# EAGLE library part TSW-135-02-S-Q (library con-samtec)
THROUGH-HOLE .025" SQ POST HEADER Source: Samtec TSW.pdf
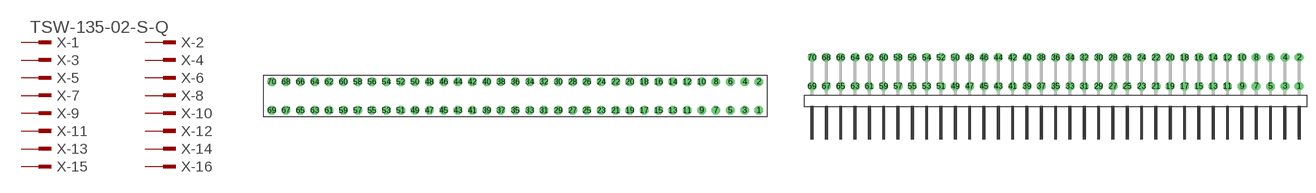
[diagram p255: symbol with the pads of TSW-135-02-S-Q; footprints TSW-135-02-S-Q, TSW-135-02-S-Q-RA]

Designator prefix X; gates -1=MPINV -2=MPIN -3=MPIN -4=MPIN -5=MPIN -6=MPIN -7=MPIN -8=MPIN -9=MPIN -10=MPIN -11=MPIN -12=MPIN -13=MPIN -14=MPIN -15=MPIN -16=MPIN -17=MPIN -18=MPIN -19=MPIN -20=MPIN -21=MPIN -22=MPIN -23=MPIN -24=MPIN -25=MPIN -26=MPIN -27=MPIN -28=MPIN -29=MPIN -30=MPIN -31=MPIN -32=MPIN -33=MPIN -34=MPIN -35=MPIN -36=MPIN -37=MPIN -38=MPIN -39=MPIN -40=MPIN -41=MPIN -42=MPIN -43=MPIN -44=MPIN -45=MPIN -46=MPIN -47=MPIN -48=MPIN -49=MPIN -50=MPIN -51=MPIN -52=MPIN -53=MPIN -54=MPIN -55=MPIN -56=MPIN -57=MPIN -58=MPIN -59=MPIN -60=MPIN -61=MPIN -62=MPIN -63=MPIN -64=MPIN -65=MPIN -66=MPIN -67=MPIN -68=MPIN -69=MPIN -70=MPIN

## TSW-135-02-S-Q (OC_FARNELL: unknown; OC_NEWARK: unknown)  [TSW-135-02-S-Q]
1  -1:1  pas
2  -2:1  pas
3  -3:1  pas
4  -4:1  pas
5  -5:1  pas
6  -6:1  pas
7  -7:1  pas
8  -8:1  pas
9  -9:1  pas
10  -10:1  pas
11  -11:1  pas
12  -12:1  pas
13  -13:1  pas
14  -14:1  pas
15  -15:1  pas
16  -16:1  pas
17  -17:1  pas
18  -18:1  pas
19  -19:1  pas
20  -20:1  pas
21  -21:1  pas
22  -22:1  pas
23  -23:1  pas
24  -24:1  pas
25  -25:1  pas
26  -26:1  pas
27  -27:1  pas
28  -28:1  pas
29  -29:1  pas
30  -30:1  pas
31  -31:1  pas
32  -32:1  pas
33  -33:1  pas
34  -34:1  pas
35  -35:1  pas
36  -36:1  pas
37  -37:1  pas
38  -38:1  pas
39  -39:1  pas
40  -40:1  pas
41  -41:1  pas
42  -42:1  pas
43  -43:1  pas
44  -44:1  pas
45  -45:1  pas
46  -46:1  pas
47  -47:1  pas
48  -48:1  pas
49  -49:1  pas
50  -50:1  pas
51  -51:1  pas
52  -52:1  pas
53  -53:1  pas
54  -54:1  pas
55  -55:1  pas
56  -56:1  pas
57  -57:1  pas
58  -58:1  pas
59  -59:1  pas
60  -60:1  pas
61  -61:1  pas
62  -62:1  pas
63  -63:1  pas
64  -64:1  pas
65  -65:1  pas
66  -66:1  pas
67  -67:1  pas
68  -68:1  pas
69  -69:1  pas
70  -70:1  pas

## TSW-135-02-S-Q-RA (OC_FARNELL: unknown; OC_NEWARK: unknown)  [TSW-135-02-S-Q-RA]
Pads as for TSW-135-02-S-Q

## Footprint TSW-135-02-S-Q (pad centres in mm)
THROUGH-HOLE .025" SQ POST HEADER Source: Samtec TSW.pdf
drill 1 pad 1.5 octagon: 1 43.18,-2.54; 2 43.18,2.54; 3 40.64,-2.54; 4 40.64,2.54; 5 38.1,-2.54; 6 38.1,2.54; 7 35.56,-2.54; 8 35.56,2.54; 9 33.02,-2.54; 10 33.02,2.54; 11 30.48,-2.54; 12 30.48,2.54; 13 27.94,-2.54; 14 27.94,2.54; 15 25.4,-2.54; 16 25.4,2.54; 17 22.86,-2.54; 18 22.86,2.54; 19 20.32,-2.54; 20 20.32,2.54; 21 17.78,-2.54; 22 17.78,2.54; 23 15.24,-2.54; 24 15.24,2.54; 25 12.7,-2.54; 26 12.7,2.54; 27 10.16,-2.54; 28 10.16,2.54; 29 7.62,-2.54; 30 7.62,2.54; 31 5.08,-2.54; 32 5.08,2.54; 33 2.54,-2.54; 34 2.54,2.54; 35 0,-2.54; 36 0,2.54; 37 -2.54,-2.54; 38 -2.54,2.54; 39 -5.08,-2.54; 40 -5.08,2.54; 41 -7.62,-2.54; 42 -7.62,2.54; 43 -10.16,-2.54; 44 -10.16,2.54; 45 -12.7,-2.54; 46 -12.7,2.54; 47 -15.24,-2.54; 48 -15.24,2.54; 49 -17.78,-2.54; 50 -17.78,2.54; 51 -20.32,-2.54; 52 -20.32,2.54; 53 -22.86,-2.54; 54 -22.86,2.54; 55 -25.4,-2.54; 56 -25.4,2.54; 57 -27.94,-2.54; 58 -27.94,2.54; 59 -30.48,-2.54; 60 -30.48,2.54; 61 -33.02,-2.54; 62 -33.02,2.54; 63 -35.56,-2.54; 64 -35.56,2.54; 65 -38.1,-2.54; 66 -38.1,2.54; 67 -40.64,-2.54; 68 -40.64,2.54; 69 -43.18,-2.54; 70 -43.18,2.54

## Footprint TSW-135-02-S-Q-RA (pad centres in mm)
THROUGH-HOLE .025" SQ POST HEADER Source: Samtec TSW.pdf
drill 1 pad 1.5 octagon: 1 43.18,1.524; 2 43.18,6.604; 3 40.64,1.524; 4 40.64,6.604; 5 38.1,1.524; 6 38.1,6.604; 7 35.56,1.524; 8 35.56,6.604; 9 33.02,1.524; 10 33.02,6.604; 11 30.48,1.524; 12 30.48,6.604; 13 27.94,1.524; 14 27.94,6.604; 15 25.4,1.524; 16 25.4,6.604; 17 22.86,1.524; 18 22.86,6.604; 19 20.32,1.524; 20 20.32,6.604; 21 17.78,1.524; 22 17.78,6.604; 23 15.24,1.524; 24 15.24,6.604; 25 12.7,1.524; 26 12.7,6.604; 27 10.16,1.524; 28 10.16,6.604; 29 7.62,1.524; 30 7.62,6.604; 31 5.08,1.524; 32 5.08,6.604; 33 2.54,1.524; 34 2.54,6.604; 35 0,1.524; 36 0,6.604; 37 -2.54,1.524; 38 -2.54,6.604; 39 -5.08,1.524; 40 -5.08,6.604; 41 -7.62,1.524; 42 -7.62,6.604; 43 -10.16,1.524; 44 -10.16,6.604; 45 -12.7,1.524; 46 -12.7,6.604; 47 -15.24,1.524; 48 -15.24,6.604; 49 -17.78,1.524; 50 -17.78,6.604; 51 -20.32,1.524; 52 -20.32,6.604; 53 -22.86,1.524; 54 -22.86,6.604; 55 -25.4,1.524; 56 -25.4,6.604; 57 -27.94,1.524; 58 -27.94,6.604; 59 -30.48,1.524; 60 -30.48,6.604; 61 -33.02,1.524; 62 -33.02,6.604; 63 -35.56,1.524; 64 -35.56,6.604; 65 -38.1,1.524; 66 -38.1,6.604; 67 -40.64,1.524; 68 -40.64,6.604; 69 -43.18,1.524; 70 -43.18,6.604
